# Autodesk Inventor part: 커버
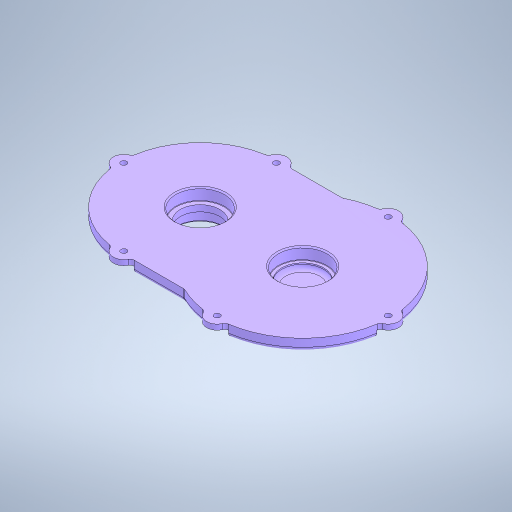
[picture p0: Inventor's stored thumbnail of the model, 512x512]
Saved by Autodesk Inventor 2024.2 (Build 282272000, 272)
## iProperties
Created: 2025-09
Part Number: 커버
Material: 알루미늄 6061
Document SubType Name: Modeling
Designer: home
Density: 2.7 g/cm^3
Appearance: 기본값
Author: jhkim
Sending System: Autodesk Inventor 2026
Preprocessor: ST-DEVELOPER v20.1
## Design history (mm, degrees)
feature "솔리드1"
node "솔리드2"
